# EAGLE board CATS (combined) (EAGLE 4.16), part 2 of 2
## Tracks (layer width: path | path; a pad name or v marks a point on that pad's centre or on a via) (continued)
N$10  (via drill 0.51) (continued)
  Bottom 0.18: TP4.T@3 42,34.5
  Bottom 0.36: 42,34.5 v42,77
  Bottom 2: TP4.T@1 TP4.T@2 TP4.T@3 TP4.T@4
N$11
  Top 0.18: R10.1 35.05,91.05 35,91 R7.2 33.05,91.05 33,91.1 | 33,91.1 C3.2 | 33,91.1 29.4,91.1 26.7,93.8 26.7,94 26.5,94.2 25.5,94.2 25.4,94.3 25.4,94.27 IC3.6
N$12
  Top 0.18: IC3.2 33,93 C3.1 34,92.95 | R7.1 35,92.9 34.95,92.95 34,92.95 | 34,92.95 R6.2
N$13
  Top 0.18: C7.2 39.05,92.95 39,93 R11.2 37.05,92.95 37,93 | IC5.3 44.73,100.27 44,101 38,101 37,100 37,93 | R10.2 37,93
N$14  (via drill 0.51)
  Top 0.18: 6,81 R14.1 3.05,81.05 3,81 | v3,77 3,81 | 3,81 Q1.3
  Bottom 0.18: 3.2,34.5 3.1,34.6 TP3.T@4 3,34.5
  Bottom 0.36: 3,34.5 v3,77
  Bottom 2: TP3.T@1 TP3.T@2 TP3.T@3 3.2,34.5
N$15
  Top 0.18: Q1.1 3.95,85 4,85 4.05,85.05 R12.1
N$16
  Top 0.18: 61.7,101.05 61.05,101.05 D2.C | 61.7,101.05 R26.2 64.95,101.05 65,101 C13.2 66.95,101.05 67,101 R23.2 | 61.7,101.05 61.7,101 61.73,100.97 IC9.3
N$17  (via drill 0.51)
  Top 0.18: v48,77 48,81 | 48,81 Q2.3 | R15.1 47.95,81.05 48,81
  Bottom 0.18: TP5.T@4 48,34.5
  Bottom 0.36: 48,34.5 v48,77
  Bottom 2: TP5.T@1 TP5.T@2 TP5.T@3 TP5.T@4
N$18
  Top 0.18: R17.1 49,87 48.95,86.95 Q2.1
N$19
  Top 0.18: R27.1 67.05,96.95 67,96.9 | IC9.2 63,97.3 63.4,96.9 67,96.9 | 67,96.9 C14.1
N$20
  Top 0.18: C14.2 67,95 66.9,95.1 62.2,95.1 61.73,94.63 IC9.6 61.73,91.73 61,91 61,87 | R30.2 61,87 | 61,87 65.25,87 68,84.25 R31.1 68,80.75
N$21  (via drill 0.51)
  Top 0.18: v68,77 R31.2
  Bottom 0.18: TP7.T@2 71.9,19.6 71.8,19.5 | TP7.T@4 68,34.5
  Bottom 0.36: 68,34.5 v68,77
  Bottom 2: TP7.T@1 71.8,19.5 | TP7.T@2 TP7.T@3 TP7.T@4
N$22
  Bottom 0.18: D14.K 93.05,102.7 93,102.75 D13.A 90.3,102.7 90,103 R21.1
N$23  (via drill 0.51)
  Top 0.18: IC6.1 92.06,86 92,86 v92,77
  Bottom 0.36: R22.SENSE2 88.3,53.3 92,57 v92,77
N$24
  Top 0.36: R22.SENSE1 86.54,78.5 86.5,78.5 87.61,79.61 IC6.8
N$25
  Top 0.18: IC6.2 90.16,86.54 89.6,87.1 87.8,87.1 87.7,87.17 IC6.6
N$26
  Top 4: TP6.T@1 TP6.T@4 80.2,34.5 | TP6.T@2 TP6.T@3 80.2,34.5 | 80.2,34.5 80.19,34.5
  Top 7.6: 80.19,34.5 R22.CURRENT2
  Bottom 4: TP6.T@1 TP6.T@4 | TP6.T@3 TP6.T@2
  Bottom 7.6: R22.CURRENT2 80.19,34.5
N$27
  Top 0.18: IC7.3 82.63,88.27 83,87.9 R20.2 84.95,87.95 85,87.9 R19.1 87.45,87.95 IC6.5
N$28
  Top 0.18: R27.2 69,92.5 73.23,88.27 IC7.6 74.4,88.27 74.3,88.2 76.4,88.2 76.55,88.05 | IC7.2 77.6,87 76.55,88.05 | R36.2 96.45,95.05 97.5,94 97.5,90 97,89.5 82.5,89.5 81.5,90.5 77.5,90.5 76.5,89.5 76.5,88 76.55,88 76.55,88.05
N$29
  Top 0.18: 101,97.3 IC10.2 | 101,97.3 101.4,96.9 104.9,96.9 105,97 C18.1 | R36.1 100.65,96.95 101,97.3
N$30
  Top 0.18: C18.2 105,95 104.9,95.1 100,95.1 99.73,94.83 IC10.6 99.73,87 | 99.73,87 99.73,86.98 97,84.25 R34.1 | 99.73,87 R35.2
N$31  (via drill 0.51)
  Top 0.18: v97,77 R34.2
  Bottom 0.18: TP9.T@3 97,34.5
  Bottom 0.36: 97,34.5 v97,77
  Bottom 2: TP9.T@1 TP9.T@2 TP9.T@3 TP9.T@4
N$32
  Top 0.18: R28.1 90.05,91.05 90,91 R25.2 88.05,91.05 88,91.1 | 88,91.1 C12.2 | 88,91.1 84.4,91.1 81.7,93.8 81.7,94 81.5,94.2 80.5,94.2 80.4,94.3 80.4,94.27 IC8.6
N$33
  Top 0.18: IC8.2 88,93 C12.1 89,92.95 | R25.1 90,92.9 89.95,92.95 89,92.95 | 89,92.95 R24.2
N$34
  Top 0.18: 89,96.9 R24.1 89,103.05 81.95,103.05 J2.CONDUCTOR 77.95,102.95 R23.1
  Bottom 0.18: R21.2 89.95,104.95 88,103 82,103 J2.CONDUCTOR
N$35
  Top 0.18: C16.2 94.05,92.95 94,93 R29.2 92.05,92.95 92,93 | IC10.3 99.73,100.27 99,101 93,101 92,100 92,93 | R28.2 92,93
N$36  (via drill 0.51)
  Top 0.18: 61,81 R32.1 58.05,81.05 58,81 | v58,77 58,81 | 58,81 Q3.3
  Bottom 0.18: 58.2,34.5 58.1,34.6 TP8.T@4 58,34.5
  Bottom 0.36: 58,34.5 v58,77
  Bottom 2: TP8.T@1 TP8.T@2 TP8.T@3 58.2,34.5
N$37
  Top 0.18: Q3.1 58.95,85 59,85 59.05,85.05 R30.1
N$38  (via drill 0.51)
  Top 0.18: v103,77 103,81 | 103,81 Q4.3 | R33.1 102.95,81.05 103,81
  Bottom 0.18: TP10.T@4 103,34.5
  Bottom 0.36: 103,34.5 v103,77
  Bottom 2: TP10.T@1 TP10.T@2 TP10.T@3 TP10.T@4
N$39
  Top 0.18: R35.1 104,87 103.95,86.95 Q4.1
N$40
  Top 0.18: 116.7,101.05 116.05,101.05 D5.C | 116.7,101.05 R41.2 119.95,101.05 120,101 C27.2 121.95,101.05 122,101 R40.2 | 116.7,101.05 116.7,101 116.73,100.97 IC13.3
N$41
  Top 0.18: R42.1 122.05,96.95 122,96.9 | IC13.2 118,97.3 118.4,96.9 122,96.9 | 122,96.9 C28.1
N$42
  Top 0.18: C28.2 122,95 121.9,95.1 117.2,95.1 116.73,94.63 IC13.6 116.73,91.73 116,91 116,87 | R55.2 116,87 | 116,87 120.25,87 123,84.25 R43.1 123,80.75
N$43  (via drill 0.51)
  Top 0.18: v123,77 R43.2
  Bottom 0.18: TP12.T@2 126.9,19.6 126.8,19.5 | TP12.T@4 123,34.5
  Bottom 0.36: 123,34.5 v123,77
  Bottom 2: TP12.T@1 126.8,19.5 | TP12.T@2 TP12.T@3 TP12.T@4
N$44
  Bottom 0.18: D16.K 148.05,102.7 148,102.75 D15.A 145.3,102.7 145,103 R53.1
N$45  (via drill 0.51)
  Top 0.18: IC14.1 147.06,86 147,86 v147,77
  Bottom 0.36: R45.SENSE2 143.3,53.3 147,57 v147,77
N$46
  Top 0.36: R45.SENSE1 141.54,78.5 141.5,78.5 142.61,79.61 IC14.8
N$47
  Top 0.18: IC14.2 145.16,86.54 144.6,87.1 142.8,87.1 142.7,87.17 IC14.6
N$48
  Top 4: TP13.T@1 TP13.T@4 135.2,34.5 | TP13.T@2 TP13.T@3 135.2,34.5 | 135.2,34.5 135.19,34.5
  Top 7.6: 135.19,34.5 R45.CURRENT2
  Bottom 4: TP13.T@1 TP13.T@4 | TP13.T@3 TP13.T@2
  Bottom 7.6: R45.CURRENT2 135.19,34.5
N$49
  Top 0.18: IC15.3 137.63,88.27 138,87.9 R44.2 139.95,87.95 140,87.9 R46.1 142.45,87.95 IC14.5
N$50
  Top 0.18: R42.2 124,92.5 128.23,88.27 IC15.6 129.4,88.27 129.3,88.2 131.4,88.2 131.55,88.05 | IC15.2 132.6,87 131.55,88.05 | R50.2 151.45,95.05 152.5,94 152.5,90 152,89.5 137.5,89.5 136.5,90.5 132.5,90.5 131.5,89.5 131.5,88 131.55,88 131.55,88.05
N$51
  Top 0.18: 156,97.3 IC16.2 | 156,97.3 156.4,96.9 159.9,96.9 160,97 C31.1 | R50.1 155.65,96.95 156,97.3
N$52
  Top 0.18: C31.2 160,95 159.9,95.1 155,95.1 154.73,94.83 IC16.6 154.73,87 | 154.73,87 154.73,86.98 152,84.25 R47.1 | 154.73,87 R57.2
N$53  (via drill 0.51)
  Top 0.18: v152,77 R47.2
  Bottom 0.18: TP14.T@3 152,34.5
  Bottom 0.36: 152,34.5 v152,77
  Bottom 2: TP14.T@1 TP14.T@2 TP14.T@3 TP14.T@4
N$54
  Top 0.18: R51.1 145.05,91.05 145,91 R48.2 143.05,91.05 143,91.1 | 143,91.1 C33.2 | 143,91.1 139.4,91.1 136.7,93.8 136.7,94 136.5,94.2 135.5,94.2 135.4,94.3 135.4,94.27 IC17.6
N$55
  Top 0.18: IC17.2 143,93 C33.1 144,92.95 | R48.1 145,92.9 144.95,92.95 144,92.95 | 144,92.95 R49.2
N$56
  Top 0.18: 144,96.9 R49.1 144,103.05 136.95,103.05 J3.CONDUCTOR 132.95,102.95 R40.1
  Bottom 0.18: R53.2 144.95,104.95 143,103 137,103 J3.CONDUCTOR
N$57
  Top 0.18: C34.2 149.05,92.95 149,93 R52.2 147.05,92.95 147,93 | IC16.3 154.73,100.27 154,101 148,101 147,100 147,93 | R51.2 147,93
N$58  (via drill 0.51)
  Top 0.18: 116,81 R54.1 113.05,81.05 113,81 | v113,77 113,81 | 113,81 Q5.3
  Bottom 0.18: 113.2,34.5 113.1,34.6 TP15.T@4 113,34.5
  Bottom 0.36: 113,34.5 v113,77
  Bottom 2: TP15.T@1 TP15.T@2 TP15.T@3 113.2,34.5
N$59
  Top 0.18: Q5.1 113.95,85 114,85 114.05,85.05 R55.1
N$60  (via drill 0.51)
  Top 0.18: v158,77 158,81 | 158,81 Q6.3 | R56.1 157.95,81.05 158,81
  Bottom 0.18: TP16.T@4 158,34.5
  Bottom 0.36: 158,34.5 v158,77
  Bottom 2: TP16.T@1 TP16.T@2 TP16.T@3 TP16.T@4
N$61
  Top 0.18: R57.1 159,87 158.95,86.95 Q6.1
N$62
  Top 0.18: 171.7,101.05 171.05,101.05 D6.C | 171.7,101.05 R59.2 174.95,101.05 175,101 C36.2 176.95,101.05 177,101 R58.2 | 171.7,101.05 171.7,101 171.73,100.97 IC18.3
N$63
  Top 0.18: R60.1 177.05,96.95 177,96.9 | IC18.2 173,97.3 173.4,96.9 177,96.9 | 177,96.9 C37.1
N$64
  Top 0.18: C37.2 177,95 176.9,95.1 172.2,95.1 171.73,94.63 IC18.6 171.73,91.73 171,91 171,87 | R73.2 171,87 | 171,87 175.25,87 178,84.25 R61.1 178,80.75
N$65  (via drill 0.51)
  Top 0.18: v178,77 R61.2
  Bottom 0.18: TP17.T@2 181.9,19.6 181.8,19.5 | 178,34.5 TP17.T@4
  Bottom 0.36: v178,77 178,34.5
  Bottom 2: 181.8,19.5 TP17.T@1 | TP17.T@2 TP17.T@3 TP17.T@4
N$66
  Bottom 0.18: D18.K 203.05,102.7 203,102.75 D17.A 200.3,102.7 200,103 R71.1
N$67  (via drill 0.51)
  Top 0.18: IC19.1 202.06,86 202,86 v202,77
  Bottom 0.36: R63.SENSE2 198.3,53.3 202,57 v202,77
N$68
  Top 0.36: R63.SENSE1 196.54,78.5 196.5,78.5 197.61,79.61 IC19.8
N$69
  Top 0.18: IC19.2 200.16,86.54 199.6,87.1 197.8,87.1 197.7,87.17 IC19.6
N$70
  Top 4: TP18.T@1 TP18.T@4 190.2,34.5 | TP18.T@2 TP18.T@3 190.2,34.5 | 190.2,34.5 190.19,34.5
  Top 7.6: 190.19,34.5 R63.CURRENT2
  Bottom 4: TP18.T@1 TP18.T@4 | TP18.T@3 TP18.T@2
  Bottom 7.6: R63.CURRENT2 190.19,34.5
N$71
  Top 0.18: IC20.3 192.63,88.27 193,87.9 R62.2 194.95,87.95 195,87.9 R64.1 197.45,87.95 IC19.5
N$72
  Top 0.18: R60.2 179,92.5 183.23,88.27 IC20.6 184.4,88.27 184.3,88.2 186.4,88.2 186.55,88.05 | IC20.2 187.6,87 186.55,88.05 | R68.2 206.45,95.05 207.5,94 207.5,90 207,89.5 192.5,89.5 191.5,90.5 187.5,90.5 186.5,89.5 186.5,88 186.55,88 186.55,88.05
N$73
  Top 0.18: 211,97.3 IC21.2 | 211,97.3 211.4,96.9 214.9,96.9 215,97 C40.1 | R68.1 210.65,96.95 211,97.3
N$74
  Top 0.18: C40.2 215,95 214.9,95.1 210,95.1 209.73,94.83 IC21.6 209.73,87 | 209.73,87 209.73,86.98 207,84.25 R65.1 | 209.73,87 R75.2
N$75  (via drill 0.51)
  Top 0.18: v207,77 R65.2
  Bottom 0.18: 207,34.5 TP19.T@3
  Bottom 0.36: v207,77 207,34.5
  Bottom 2: TP19.T@1 TP19.T@2 TP19.T@3 TP19.T@4
N$76
  Top 0.18: R69.1 200.05,91.05 200,91 R66.2 198.05,91.05 198,91.1 | 198,91.1 C42.2 | 198,91.1 194.4,91.1 191.7,93.8 191.7,94 191.5,94.2 190.5,94.2 190.4,94.3 190.4,94.27 IC22.6
N$77
  Top 0.18: IC22.2 198,93 C42.1 199,92.95 | R66.1 200,92.9 199.95,92.95 199,92.95 | 199,92.95 R67.2
N$78
  Top 0.18: 199,96.9 R67.1 199,103.05 191.95,103.05 J4.CONDUCTOR 187.95,102.95 R58.1
  Bottom 0.18: R71.2 199.7,104.95 197.75,103 191.75,103 190,104.75 J4.CONDUCTOR
N$79
  Top 0.18: C43.2 204.05,92.95 204,93 R70.2 202.05,92.95 202,93 | IC21.3 209.73,100.27 209,101 203,101 202,100 202,93 | R69.2 202,93
N$80  (via drill 0.51)
  Top 0.18: 171,81 R72.1 168.05,81.05 168,81 | v168,77 168,81 | 168,81 Q7.3
  Bottom 0.18: 168.2,34.5 168.1,34.6 TP20.T@4 168,34.5
  Bottom 0.36: 168,34.5 v168,77
  Bottom 2: TP20.T@1 TP20.T@2 TP20.T@3 168.2,34.5
N$81
  Top 0.18: Q7.1 168.95,85 169,85 169.05,85.05 R73.1
N$82  (via drill 0.51)
  Top 0.18: 213,81 v213,77 | 213,81 Q8.3 | R74.1 212.95,81.05 213,81
  Bottom 0.18: 213,34.5 TP21.T@4
  Bottom 0.36: v213,77 213,34.5
  Bottom 2: TP21.T@1 TP21.T@2 TP21.T@3 TP21.T@4
N$83
  Top 0.18: R75.1 214,87 213.95,86.95 Q8.1
N$84
  Top 0.18: 226.7,101.05 226.05,101.05 D7.C | 226.7,101.05 R77.2 229.95,101.05 230,101 C45.2 232.05,101.05 232.25,101.25 R76.2 | 226.7,101.05 226.7,101 226.73,100.97 IC23.3
N$85
  Top 0.18: R78.1 232.05,96.95 232,96.9 | IC23.2 228,97.3 228.4,96.9 232,96.9 | 232,96.9 C46.1
N$86
  Top 0.18: C46.2 232,95 231.9,95.1 227.2,95.1 226.73,94.63 IC23.6 226.73,91.73 226,91 226,87 | R91.2 226,87 | 226,87 230.25,87 233,84.25 R79.1 233,80.75
N$87  (via drill 0.51)
  Top 0.18: v233,77 R79.2
  Bottom 0.18: TP22.T@2 236.9,19.6 236.8,19.5 | TP22.T@4 233,34.5
  Bottom 0.36: 233,34.5 v233,77
  Bottom 2: 236.8,19.5 TP22.T@1 | TP22.T@2 TP22.T@3 TP22.T@4
N$88
  Bottom 0.18: D19.A 257.75,102.7 257.75,102.75 257.8,102.7 D19.A | D19.A D20.K | R89.1 255,103 255.3,102.7 D19.A
N$89  (via drill 0.51)
  Top 0.18: IC24.1 257.06,86 257,86 v257,77
  Bottom 0.36: R81.SENSE2 253.3,53.3 257,57 v257,77
N$90
  Top 0.36: R81.SENSE1 251.54,78.5 251.5,78.5 252.61,79.61 IC24.8
N$91
  Top 0.18: IC24.2 255.16,86.54 254.6,87.1 252.8,87.1 252.7,87.17 IC24.6
N$92
  Top 4: TP23.T@1 TP23.T@4 245.2,34.5 | TP23.T@2 TP23.T@3 245.2,34.5 | 245.2,34.5 245.19,34.5
  Top 7.6: 245.19,34.5 R81.CURRENT2
  Bottom 4: TP23.T@1 TP23.T@4 | TP23.T@3 TP23.T@2
  Bottom 7.6: R81.CURRENT2 245.19,34.5
N$93
  Top 0.18: IC25.3 247.63,88.27 248,87.9 R80.2 249.95,87.95 250,87.9 R82.1 252.45,87.95 IC24.5
N$94
  Top 0.18: R78.2 234,92.5 238.23,88.27 IC25.6 239.4,88.27 239.3,88.2 241.4,88.2 241.55,88.05 | IC25.2 242.6,87 241.55,88.05 | 241.55,88.05 241.55,88 241.5,88 241.5,89.5 242.5,90.5 246.5,90.5 247.5,89.5 262,89.5 262.5,90 262.5,94.25 261.75,95 R86.2
N$95
  Top 0.18: 266,97.3 IC26.2 | 266,97.3 266.4,96.9 269.9,96.9 270,97 C49.1 | R86.1 259.05,95.55 259.75,96.25 265,96.25 266,97.25 266,97.3
N$96
  Top 0.18: C49.2 270,95 269.9,95.1 265,95.1 264.73,94.83 IC26.6 264.73,87 | 264.73,87 264.73,86.98 262,84.25 R83.1 | 264.73,87 R93.2
N$97  (via drill 0.51)
  Top 0.18: v262,77 R83.2
  Bottom 0.18: TP24.T@3 262,34.5
  Bottom 0.36: 262,34.5 v262,77
  Bottom 2: TP24.T@1 TP24.T@2 TP24.T@3 TP24.T@4
N$98
  Top 0.18: R87.1 255.05,91.05 255,91 R84.2 253.05,91.05 253,91.1 | 253,91.1 C51.2 | 253,91.1 249.4,91.1 246.7,93.8 246.7,94 246.5,94.2 245.5,94.2 245.4,94.3 245.4,94.27 IC27.6
N$99
  Top 0.18: IC27.2 253,93 C51.1 254,92.95 | R84.1 255,92.9 254.95,92.95 254,92.95 | 254,92.95 R85.2
N$100
  Top 0.18: 254,96.9 R85.1 254,103.05 246.95,103.05 J5.CONDUCTOR 242.95,102.95 R76.1
  Bottom 0.18: R89.2 254.95,104.95 253,103 247,103 J5.CONDUCTOR
N$101
  Top 0.18: C52.2 259.05,92.95 259,93 R88.2 257.75,92.95 | 257.75,92.95 257.05,92.95 257,93 R87.2 | IC26.3 264.73,97.48 264,96.75 258.5,96.75 257.75,96 257.75,92.95
N$102  (via drill 0.51)
  Top 0.18: 226,81 R90.1 223.05,81.05 223,81 | v223,77 223,81 | 223,81 Q9.3
  Bottom 0.18: 223.2,34.5 223.1,34.6 TP25.T@4 223,34.5
  Bottom 0.36: 223,34.5 v223,77
  Bottom 2: TP25.T@1 TP25.T@2 TP25.T@3 223.2,34.5
N$103
  Top 0.18: Q9.1 223.95,85 224,85 224.05,85.05 R91.1
N$104  (via drill 0.51)
  Top 0.18: v268,77 268,81 | 268,81 Q10.3 | R92.1 267.95,81.05 268,81
  Bottom 0.18: TP26.T@4 268,34.5
  Bottom 0.36: 268,34.5 v268,77
  Bottom 2: TP26.T@1 TP26.T@2 TP26.T@3 TP26.T@4
N$105
  Top 0.18: R93.1 269,87 268.95,86.95 Q10.1
N$106
  Top 0.4: 55,0 55,12
N$107
  Top 0.4: 110,0 110,12
N$108
  Top 0.4: 165,0 165,12
N$109
  Top 0.4: 220,0 220,12
N$110
  Top 0.18: 6.7,101.05 6.05,101.05 D1.C | 6.7,101.05 R8.2 9.95,101.05 10,101 C4.2 R5.2 12,101 | 6.7,101.05 6.7,101 6.73,100.97 IC4.3
N$111
  Top 0.4: 275,0 275,12
N$112
  Bottom 0.5: P1.9 310.16,91.66 308,89.5 305.5,89.5 305,89 305,58 298,51 | 293,51 298,51 | 298,51 F1.1A
N$113
  Top 0.18: D8.A 303.77,94.77 304,95 R94.2 307,95 307.25,94.75 307.32,94.75 P1.4
N$114
  Top 0.18: R9.1 12.05,96.95 12,96.9 | IC4.2 8,97.3 8.4,96.9 12,96.9 | 12,96.9 C5.1
N$115
  Top 0.18: C5.2 12,95 11.9,95.1 7.2,95.1 6.73,94.63 IC4.6 6.73,91.73 6,91 6,87 | R12.2 6,87 | 6,87 10.25,87 13,84.25 R13.1
N$116
  Bottom 0.36: 296,100.5 300.5,100.5 303,103 307.5,103 307.5,103.06 P1.1
  Bottom 0.5: 291,100.28 291,100.5 291.08,100.42 Q11.2 | 296,100.5 295.97,100.5 HS1.2
  Bottom 1: HS1.2 295.97,100 296,100 295.72,100.28 291,100.28 HS1.1
N$117  (via drill 0.51)
  Top 0.18: v13,77 R13.2
  Bottom 0.18: TP2.T@2 16.9,19.6 16.8,19.5 | TP2.T@4 13,34.5
  Bottom 0.36: 13,34.5 v13,77
  Bottom 2: TP2.T@1 16.8,19.5 | TP2.T@2 TP2.T@3 TP2.T@4
N$118
  Top 0.18: R96.CW 302.77,92.23 302.5,92.5 D8.C 300.75,93 | Q11.1 288.54,93.71 289.25,93 300.75,93 | D9.C 301.5,97 300.75,96.25 300.75,93
  Bottom 0.18: R96.W 300.2,86.9 302.74,89.44 R96.CW
N$119
  Top 0.18: D9.A 303.75,97 303.95,97.2 303.95,97.5 | R95.2 303.95,97.5 | 303.95,97.5 304,97.5 304.07,97.57 P1.3
N$120  (via drill 0.51)
  Top 0.18: P1.2 307.25,100.31 307.25,100.25 306.47,101.03 D10.3 | R97.1 293.55,86.95 v293.5,87
  Bottom 0.18: P1.2 307.25,100.31 307.25,100.25 294,87 v293.5,87
N$121
  Bottom 0.18: D11.A D12.K | D11.A 38,102.75 | R3.1 35,103 35.3,102.7 D11.A
N$122
  Top 0.18: J13.CONDUCTOR 11.49,218.5 11.5,218.5 9.99,216.99 R98.1
  Bottom 0.18: R174.2 21.55,211.05 20.5,210 15,210 11.5,213.5 11.5,218.5 11.49,218.5 J13.CONDUCTOR
N$123
  Top 0.178: 7.45,204.95 C54.2 R99.2 7.95,207.49 8.97,206.47 9.86,206.47 9.99,206.35 R98.2 11.7,206.41 12.02,206.09 | 12.02,206.09 D21.C | 12.02,206.09 12.02,205.2 12.91,204.31 14.3,204.31 14.43,204.19 IC28.3
N$124  (via drill 0.51)
  Top 0.178: v11.51,199.62 IC29.1
  Bottom 0.381: R102.SENSE2 11.51,189.71 14.3,192.5 14.3,194.66 11.51,197.46 v11.51,199.62
N$125  (via drill 0.51)
  Top 0.178: v10.11,199.62 9.22,200.5 7.32,200.5 7.19,200.63 IC29.8
  Bottom 0.381: R102.SENSE1 11.51,196.44 10.11,197.84 v10.11,199.62
N$126
  Top 0.178: IC29.6 9.35,201.9 9.99,201.27 IC29.2
N$127
  Top 0.178: R100.2 16.32,201 16.34,201.01 | 14.43,205.33 14.3,205.46 IC28.2 14.43,205.46 14.3,205.33 15.7,205.33 16.34,204.7 16.34,201.01 | 16.34,201.01 C55.1 14.05,201.01 12.78,202.16 12.4,202.54 12.4,203.17 12.14,203.43 9.86,203.43 8.97,202.54 IC29.5 7.07,202.69 5.07,202.69 R190.1
N$128
  Top 0.178: 19.51,204.19 IC28.6 18.11,204.19 17.73,203.81 17.73,202.28 18.22,201.79 C55.2 18.11,201.01 18.18,200.95 R101.1
N$129
  Top 3.81: 6.81,149.2 TP27.T@3 | TP27.T@2 6.9,149.11 6.81,149.2 | TP27.T@4 3.1,149.32 3.13,149.32 3.1,149.3 TP27.T@4 | TP27.T@1 TP27.T@4 | TP27.T@4 3.1,149.07 3.13,149.07 3.25,149.2 6.81,149.2
  Top 7.62: R102.CURRENT2 5.16,149.32
  Bottom 2.54: 5.29,149.45 5.16,149.45 | 4.87,149.24 5.07,149.24 5.29,149.45 | 5.29,149.45 5.03,149.2 6.81,149.2 TP27.T@3
  Bottom 7.62: R102.CURRENT2 5.16,149.45 5.16,149.32 | 4.87,149.24 4.87,134.71
N$130  (via drill 0.51)
  Top 0.254: R101.2 20.57,198.3 v21.54,197.33
  Bottom 0.254: TP28.T@2 21.8,134.2 21.8,134.21 21.79,134.2 | TP28.T@3 21.8,149.2 21.9,149.09 | TP28.T@3 21.54,149.2 21.42,149.07 21.29,149.2 | 21.92,149.07 21.9,149.07 TP28.T@3
  Bottom 0.381: v21.54,197.33 21.92,196.95 21.92,149.07
  Bottom 2.54: TP28.T@1 21.79,134.2 | TP28.T@2 21.9,149.09 | 21.29,149.2 TP28.T@4
N$131
  Top 0.18: J11.CONDUCTOR 36.49,218.25 36.5,218.25 34.99,216.74 R103.1
  Bottom 0.18: R173.2 46.55,211.05 45.5,210 40,210 36.5,213.5 36.5,218 36.49,218 J11.CONDUCTOR
N$132
  Top 0.178: 32.45,204.95 C57.2 R104.2 32.95,207.49 33.97,206.47 34.86,206.47 34.99,206.35 R103.2 36.7,206.41 37.02,206.09 | 37.02,206.09 D22.C | 37.02,206.09 37.02,205.2 37.91,204.31 39.3,204.31 39.43,204.19 IC30.3
N$133  (via drill 0.51)
  Top 0.178: v36.51,199.62 IC31.1
  Bottom 0.381: R107.SENSE2 36.51,189.71 39.3,192.5 39.3,194.66 36.51,197.46 v36.51,199.62
N$134  (via drill 0.51)
  Top 0.178: v35.11,199.62 34.22,200.5 32.32,200.5 32.19,200.63 IC31.8
  Bottom 0.381: R107.SENSE1 36.51,196.44 35.11,197.84 v35.11,199.62
N$135
  Top 0.178: IC31.6 34.35,201.9 34.99,201.27 IC31.2
N$136
  Top 0.178: R105.2 41.32,201 41.34,201.01 | 39.43,205.33 39.3,205.46 IC30.2 39.43,205.46 39.3,205.33 40.7,205.33 41.34,204.7 41.34,201.01 | 41.34,201.01 C58.1 39.05,201.01 37.78,202.16 37.4,202.54 37.4,203.17 37.15,203.43 34.86,203.43 33.97,202.54 IC31.5 32.06,202.82 30.07,202.82 R189.1
N$137
  Top 0.178: 44.51,204.19 IC30.6 43.11,204.19 42.73,203.81 42.73,202.28 43.22,201.79 C58.2 43.11,201.01 43.18,200.95 R106.1
N$138
  Top 3.81: 31.81,149.2 TP29.T@3 | TP29.T@2 31.9,149.11 31.81,149.2 | TP29.T@4 28.1,149.32 28.13,149.32 28.1,149.3 TP29.T@4 | TP29.T@1 TP29.T@4 | TP29.T@4 28.1,149.07 28.13,149.07 28.25,149.2 31.81,149.2
  Top 7.62: R107.CURRENT2 30.16,149.32
  Bottom 2.54: 30.29,149.45 30.16,149.45 | 29.87,149.24 30.07,149.24 30.29,149.45 | 30.29,149.45 30.03,149.2 31.81,149.2 TP29.T@3
  Bottom 7.62: R107.CURRENT2 30.16,149.45 30.16,149.32 | 29.87,149.24 29.87,134.71
N$139  (via drill 0.51)
  Top 0.254: R106.2 45.57,198.3 v46.54,197.33
  Bottom 0.254: TP30.T@2 46.8,134.2 46.8,134.21 46.79,134.2 | TP30.T@3 46.8,149.2 46.9,149.09 | TP30.T@3 46.54,149.2 46.42,149.07 46.29,149.2 | 46.92,149.07 46.9,149.07 TP30.T@3
  Bottom 0.381: v46.54,197.33 46.92,196.95 46.92,149.07
  Bottom 2.54: TP30.T@1 46.79,134.2 | TP30.T@2 46.9,149.09 | 46.29,149.2 TP30.T@4
N$140
  Top 0.18: J9.CONDUCTOR 61.49,218.25 61.5,218.25 59.99,216.74 R108.1
  Bottom 0.18: R171.2 71.55,211.05 70.5,210 65,210 61.5,213.5 61.5,218 61.49,218 J9.CONDUCTOR
N$141
  Top 0.178: 57.45,204.95 C60.2 R109.2 57.95,207.49 58.97,206.47 59.86,206.47 59.99,206.35 R108.2 61.7,206.41 62.02,206.09 | 62.02,206.09 D23.C | 62.02,206.09 62.02,205.2 62.91,204.31 64.3,204.31 64.43,204.19 IC32.3
N$142  (via drill 0.51)
  Top 0.178: v61.51,199.62 IC33.1
  Bottom 0.381: R112.SENSE2 61.51,189.71 64.3,192.5 64.3,194.66 61.51,197.46 v61.51,199.62
N$143  (via drill 0.51)
  Top 0.178: v60.11,199.62 59.22,200.5 57.32,200.5 57.19,200.63 IC33.8
  Bottom 0.381: R112.SENSE1 61.51,196.44 60.11,197.84 v60.11,199.62
N$144
  Top 0.178: IC33.6 59.35,201.9 59.99,201.27 IC33.2
N$145  (via drill 0.51)
  Top 0.18: 277.6,109.5 277.5,109.5 277.46,109.54 IC11.3 | 277.6,109.5 C19.2 | 277.6,109.5 277.6,109.16 v279.25,107.5
  Bottom 0.18: F1.2A 277.84,50.9 277.8,50.9 277.9,50.8 | v279.25,107.5 279.25,98.75 287,91 287,77 289.8,74.2 289.8,65.9 291,64.7 292,64.7
  Bottom 0.5: D3.2 292,64.7 292,59.6 283.2,50.8 277.9,50.8
N$146
  Top 0.18: C20.2 277,102.5 | C20.2 R38.1 | C20.2 275.05,102.7 275,102.75 R37.2 275,103.5 274,104.5 IC11.1
N$147
  Top 0.178: R110.2 66.32,201 66.34,201.01 | 64.43,205.33 64.3,205.46 IC32.2 64.43,205.46 64.3,205.33 65.7,205.33 66.34,204.7 66.34,201.01 | 66.34,201.01 C61.1 64.05,201.01 62.78,202.16 62.4,202.54 62.4,203.17 62.15,203.43 59.86,203.43 58.97,202.54 IC33.5 57.06,202.82 55.07,202.82 R188.1
N$148
  Top 0.178: 69.51,204.19 IC32.6 68.11,204.19 67.73,203.81 67.73,202.28 68.22,201.79 C61.2 68.11,201.01 68.18,200.95 R111.1
N$149
  Top 3.81: 56.81,149.2 TP31.T@3 | TP31.T@2 56.9,149.11 56.81,149.2 | TP31.T@4 53.1,149.32 53.13,149.32 53.1,149.3 TP31.T@4 | TP31.T@1 TP31.T@4 | TP31.T@4 53.1,149.07 53.13,149.07 53.26,149.2 56.81,149.2
  Top 7.62: R112.CURRENT2 55.16,149.32
  Bottom 2.54: 55.29,149.45 55.16,149.45 | 54.87,149.24 55.07,149.24 55.29,149.45 | 55.29,149.45 55.03,149.2 56.81,149.2 TP31.T@3
  Bottom 7.62: R112.CURRENT2 55.16,149.45 55.16,149.32 | 54.87,149.24 54.87,134.71
N$150  (via drill 0.51)
  Top 0.254: R111.2 70.57,198.3 v71.54,197.33
  Bottom 0.254: TP32.T@2 71.8,134.2 71.8,134.21 71.79,134.2 | TP32.T@3 71.8,149.2 71.9,149.09 | TP32.T@3 71.54,149.2 71.42,149.07 71.29,149.2 | 71.92,149.07 71.9,149.07 TP32.T@3
  Bottom 0.381: v71.54,197.33 71.92,196.95 71.92,149.07
  Bottom 2.54: 71.79,134.2 TP32.T@1 | 71.9,149.09 TP32.T@2 | 71.29,149.2 TP32.T@4
N$151
  Top 0.18: J12.CONDUCTOR 86.49,218.25 86.5,218.25 84.99,216.74 R113.1
  Bottom 0.18: R175.2 96.55,211.05 95.5,210 90,210 86.5,213.5 86.5,218.5 86.49,218.5 J12.CONDUCTOR
N$152
  Top 0.178: 82.45,204.95 C63.2 R114.2 82.95,207.49 83.97,206.47 84.86,206.47 84.99,206.35 R113.2 86.7,206.41 87.02,206.09 | 87.02,206.09 D24.C | 87.02,206.09 87.02,205.2 87.91,204.31 89.3,204.31 89.43,204.19 IC34.3
N$153  (via drill 0.51)
  Top 0.178: v86.51,199.62 IC35.1
  Bottom 0.381: R117.SENSE2 86.51,189.71 89.3,192.5 89.3,194.66 86.51,197.46 v86.51,199.62
N$154  (via drill 0.51)
  Top 0.178: v85.11,199.62 84.22,200.5 82.32,200.5 82.19,200.63 IC35.8
  Bottom 0.381: R117.SENSE1 86.51,196.44 85.11,197.84 v85.11,199.62
N$155
  Top 0.178: IC35.6 84.35,201.9 84.99,201.27 IC35.2
N$156
  Top 0.178: R115.2 91.32,201 91.34,201.01 | 89.43,205.33 89.3,205.46 IC34.2 89.43,205.46 89.3,205.33 90.7,205.33 91.34,204.7 91.34,201.01 | 91.34,201.01 C64.1 89.05,201.01 87.78,202.16 87.4,202.54 87.4,203.17 87.14,203.43 84.86,203.43 83.97,202.54 IC35.5 82.06,202.82 80.07,202.82 R187.1
N$157
  Top 0.178: 94.51,204.19 IC34.6 93.11,204.19 92.73,203.81 92.73,202.28 93.22,201.79 C64.2 93.11,201.01 93.18,200.95 R116.1
N$158
  Top 3.81: 81.81,149.2 TP33.T@3 | TP33.T@2 81.9,149.11 81.81,149.2 | TP33.T@4 78.1,149.32 78.13,149.32 78.1,149.3 TP33.T@4 | TP33.T@1 TP33.T@4 | TP33.T@4 78.1,149.07 78.13,149.07 78.25,149.2 81.81,149.2
  Top 7.62: R117.CURRENT2 80.16,149.32
  Bottom 2.54: 80.29,149.45 80.16,149.45 | 79.87,149.24 80.07,149.24 80.29,149.45 | 80.29,149.45 80.03,149.2 81.81,149.2 TP33.T@3
  Bottom 7.62: R117.CURRENT2 80.16,149.45 80.16,149.32 | 79.87,149.24 79.87,134.71
N$159  (via drill 0.51)
  Top 0.254: R116.2 95.57,198.3 v96.54,197.33
  Bottom 0.254: TP34.T@2 96.8,134.2 96.8,134.21 96.79,134.2 | TP34.T@3 96.8,149.2 96.9,149.09 | TP34.T@3 96.54,149.2 96.42,149.07 96.29,149.2 | 96.92,149.07 96.9,149.07 TP34.T@3
  Bottom 0.381: v96.54,197.33 96.92,196.95 96.92,149.07
  Bottom 2.54: 96.79,134.2 TP34.T@1 | 96.9,149.09 TP34.T@2 | 96.29,149.2 TP34.T@4
N$160
  Top 0.18: J10.CONDUCTOR 111.49,218.5 111.5,218.5 109.99,216.99 R118.1
  Bottom 0.18: R172.2 121.55,211.05 120.5,210 115,210 111.5,213.5 111.5,218.5 111.49,218.5 J10.CONDUCTOR
N$161
  Top 0.178: 107.45,204.95 C66.2 R119.2 107.95,207.49 108.97,206.47 109.86,206.47 109.99,206.35 R118.2 111.7,206.41 112.02,206.09 | 112.02,206.09 D25.C | 112.02,206.09 112.02,205.2 112.91,204.31 114.3,204.31 114.43,204.19 IC36.3
N$162  (via drill 0.51)
  Top 0.178: v111.51,199.62 IC37.1
  Bottom 0.381: R122.SENSE2 111.51,189.71 114.3,192.5 114.3,194.66 111.51,197.46 v111.51,199.62
N$163  (via drill 0.51)
  Top 0.178: v110.11,199.62 109.22,200.5 107.32,200.5 107.19,200.63 IC37.8
  Bottom 0.381: R122.SENSE1 111.51,196.44 110.11,197.84 v110.11,199.62
N$164
  Top 0.178: IC37.6 109.35,201.9 109.99,201.27 IC37.2
N$165
  Top 0.178: R120.2 116.32,201 116.34,201.01 | 114.43,205.33 114.3,205.46 IC36.2 114.43,205.46 114.3,205.33 115.7,205.33 116.34,204.7 116.34,201.01 | 116.34,201.01 C67.1 114.05,201.01 112.78,202.16 112.4,202.54 112.4,203.17 112.14,203.43 109.86,203.43 108.97,202.54 IC37.5 107.06,202.82 105.07,202.82 R186.1
N$166
  Top 0.178: 119.51,204.19 IC36.6 118.11,204.19 117.73,203.81 117.73,202.28 118.22,201.79 C67.2 118.11,201.01 118.18,200.95 R121.1
N$167
  Top 3.81: 106.81,149.2 TP35.T@3 | TP35.T@2 106.9,149.11 106.81,149.2 | TP35.T@4 103.1,149.32 103.13,149.32 103.1,149.3 TP35.T@4 | TP35.T@4 TP35.T@1 | TP35.T@4 103.1,149.07 103.13,149.07 103.25,149.2 106.81,149.2
  Top 7.62: R122.CURRENT2 105.16,149.32
  Bottom 2.54: 105.29,149.45 105.16,149.45 | 104.87,149.24 105.07,149.24 105.29,149.45 | 105.29,149.45 105.03,149.2 106.81,149.2 TP35.T@3
  Bottom 7.62: R122.CURRENT2 105.16,149.45 105.16,149.32 | 104.87,149.24 104.87,134.71
N$168  (via drill 0.51)
  Top 0.254: R121.2 120.57,198.3 v121.54,197.33
  Bottom 0.254: TP36.T@2 121.8,134.2 121.8,134.21 121.79,134.2 | TP36.T@3 121.8,149.2 121.9,149.09 | TP36.T@3 121.54,149.2 121.42,149.07 121.29,149.2 | 121.92,149.07 121.9,149.07 TP36.T@3 | 121.92,196.95 v121.54,197.33
  Bottom 0.381: 121.92,149.07 121.92,196.95
  Bottom 2.54: 121.79,134.2 TP36.T@1 | 121.9,149.09 TP36.T@2 | TP36.T@4 121.29,149.2
N$169
  Top 0.18: J8.CONDUCTOR 136.49,218.5 136.5,218.5 134.99,216.99 R123.1
  Bottom 0.18: R170.2 146.55,211.05 145.5,210 140,210 136.5,213.5 136.5,218.5 136.49,218.5 J8.CONDUCTOR
N$170
  Top 0.178: 132.45,204.95 C69.2 R124.2 132.95,207.49 133.97,206.47 134.86,206.47 134.99,206.35 R123.2 136.7,206.41 137.02,206.09 | 137.02,206.09 D26.C | 137.02,206.09 137.02,205.2 137.91,204.31 139.3,204.31 139.43,204.19 IC38.3
N$171  (via drill 0.51)
  Top 0.178: v136.51,199.62 IC39.1
  Bottom 0.381: R127.SENSE2 136.51,189.71 139.3,192.5 139.3,194.66 136.51,197.46 v136.51,199.62
N$172  (via drill 0.51)
  Top 0.178: v135.11,199.62 134.22,200.5 132.32,200.5 132.19,200.63 IC39.8
  Bottom 0.381: R127.SENSE1 136.51,196.44 135.11,197.84 v135.11,199.62
N$173
  Top 0.178: IC39.6 134.35,201.9 134.99,201.27 IC39.2
N$174
  Top 0.178: R125.2 141.32,201 141.34,201.01 | 139.43,205.33 139.3,205.46 IC38.2 139.43,205.46 139.3,205.33 140.7,205.33 141.34,204.7 141.34,201.01 | 141.34,201.01 C70.1 139.05,201.01 137.78,202.16 137.4,202.54 137.4,203.17 137.15,203.43 134.86,203.43 133.97,202.54 IC39.5 132.06,202.82 130.07,202.82 R185.1
N$175
  Top 0.178: 144.51,204.19 IC38.6 143.11,204.19 142.73,203.81 142.73,202.28 143.22,201.79 C70.2 143.11,201.01 143.18,200.95 R126.1
N$176
  Top 3.81: 131.81,149.2 TP37.T@3 | TP37.T@2 131.9,149.11 131.81,149.2 | TP37.T@4 128.1,149.32 128.13,149.32 128.1,149.3 TP37.T@4 | TP37.T@1 TP37.T@4 | TP37.T@4 128.1,149.07 128.13,149.07 128.25,149.2 131.81,149.2
  Top 7.62: R127.CURRENT2 130.16,149.32
  Bottom 2.54: 130.29,149.45 130.16,149.45 | 129.87,149.24 130.07,149.24 130.29,149.45 | 130.29,149.45 130.03,149.2 131.81,149.2 TP37.T@3
  Bottom 7.62: R127.CURRENT2 130.16,149.45 130.16,149.32 | 129.87,149.24 129.87,134.71
N$177  (via drill 0.51)
  Top 0.254: R126.2 145.57,198.3 v146.54,197.33
  Bottom 0.254: TP38.T@2 146.8,134.2 146.8,134.21 146.79,134.2 | TP38.T@3 146.8,149.2 146.9,149.09 | TP38.T@3 146.54,149.2 146.42,149.07 146.29,149.2 | 146.92,149.07 146.9,149.07 TP38.T@3 | 146.92,196.95 v146.54,197.33
  Bottom 0.381: 146.92,149.07 146.92,196.95
  Bottom 2.54: TP38.T@1 146.79,134.2 | TP38.T@2 146.9,149.09 | 146.29,149.2 TP38.T@4
N$178
  Top 0.18: J6.CONDUCTOR 161.49,218.25 161.5,218.25 159.99,216.74 R128.1
  Bottom 0.18: R165.2 171.55,211.05 170.5,210 165,210 161.5,213.5 161.5,218.5 161.49,218.5 J6.CONDUCTOR
N$179
  Top 0.178: 157.45,204.95 C72.2 R129.2 157.95,207.49 158.97,206.47 159.86,206.47 159.99,206.35 R128.2 161.7,206.41 162.02,206.09 | 162.02,206.09 D27.C | 162.02,206.09 162.02,205.2 162.91,204.31 164.3,204.31 164.43,204.19 IC40.3
N$180  (via drill 0.51)
  Top 0.178: v161.51,199.62 IC41.1
  Bottom 0.381: R132.SENSE2 161.51,189.71 164.3,192.5 164.3,194.66 161.51,197.46 v161.51,199.62
N$181  (via drill 0.51)
  Top 0.178: v160.11,199.62 159.22,200.5 157.32,200.5 157.19,200.63 IC41.8
  Bottom 0.381: R132.SENSE1 161.51,196.44 160.11,197.84 v160.11,199.62
N$182
  Top 0.178: IC41.6 159.35,201.9 159.99,201.27 IC41.2
N$183
  Top 0.178: R130.2 166.32,201 166.34,201.01 | 164.43,205.33 164.3,205.46 IC40.2 164.43,205.46 164.3,205.33 165.7,205.33 166.34,204.7 166.34,201.01 | 166.34,201.01 C73.1 164.05,201.01 162.78,202.16 162.4,202.54 162.4,203.17 162.15,203.43 159.86,203.43 158.97,202.54 IC41.5 157.06,202.82 155.07,202.82 R184.1
N$184
  Top 0.178: 169.51,204.19 IC40.6 168.11,204.19 167.73,203.81 167.73,202.28 168.22,201.79 C73.2 168.11,201.01 168.18,200.95 R131.1
N$185
  Top 3.81: 156.81,149.2 TP39.T@3 | TP39.T@2 156.9,149.11 156.81,149.2 | TP39.T@4 153.1,149.32 153.13,149.32 153.1,149.3 TP39.T@4 | TP39.T@1 TP39.T@4 | TP39.T@4 153.1,149.07 153.13,149.07 153.25,149.2 156.81,149.2
  Top 7.62: R132.CURRENT2 155.16,149.32
  Bottom 2.54: 155.29,149.45 155.16,149.45 | 154.87,149.24 155.07,149.24 155.29,149.45 | 155.29,149.45 155.03,149.2 156.81,149.2 TP39.T@3
  Bottom 7.62: R132.CURRENT2 155.16,149.45 155.16,149.32 | 154.87,149.24 154.87,134.71
N$186  (via drill 0.51)
  Top 0.254: R131.2 170.57,198.3 v171.54,197.33
  Bottom 0.254: TP40.T@2 171.8,134.2 171.8,134.21 171.79,134.2 | TP40.T@3 171.8,149.2 171.9,149.09 | TP40.T@3 171.54,149.2 171.42,149.07 171.29,149.2 | 171.92,149.07 171.9,149.07 TP40.T@3
  Bottom 0.381: v171.54,197.33 171.92,196.95 171.92,149.07
  Bottom 2.54: TP40.T@1 171.79,134.2 | TP40.T@2 171.9,149.09 | 171.29,149.2 TP40.T@4
N$187
  Top 0.18: J7.CONDUCTOR 186.49,218.25 186.5,218.25 184.99,216.74 R133.1
  Bottom 0.18: R168.2 196.55,211.05 195.5,210 190,210 186.5,213.5 186.5,218 186.49,218 J7.CONDUCTOR
N$188
  Top 0.178: 182.45,204.95 C75.2 R134.2 182.95,207.49 183.97,206.47 184.86,206.47 184.99,206.35 R133.2 186.7,206.41 187.02,206.09 | 187.02,206.09 D28.C | 187.02,206.09 187.02,205.2 187.91,204.31 189.3,204.31 189.43,204.19 IC42.3
N$189  (via drill 0.51)
  Top 0.178: v186.51,199.62 IC43.1
  Bottom 0.381: R137.SENSE2 186.51,189.71 189.3,192.5 189.3,194.66 186.51,197.46 v186.51,199.62
N$190  (via drill 0.51)
  Top 0.178: v185.11,199.62 184.22,200.5 182.32,200.5 182.19,200.63 IC43.8
  Bottom 0.381: R137.SENSE1 186.51,196.44 185.11,197.84 v185.11,199.62
N$191
  Top 0.178: IC43.6 184.35,201.9 184.99,201.27 IC43.2
N$192
  Top 0.178: R135.2 191.32,201 191.34,201.01 | 189.43,205.33 189.3,205.46 IC42.2 189.43,205.46 189.3,205.33 190.7,205.33 191.34,204.7 191.34,201.01 | 191.34,201.01 C76.1 189.05,201.01 187.78,202.16 187.4,202.54 187.4,203.17 187.15,203.43 184.86,203.43 183.97,202.54 IC43.5 182.06,202.82 180.07,202.82 R183.1
N$193
  Top 0.178: 194.51,204.19 IC42.6 193.11,204.19 192.73,203.81 192.73,202.28 193.22,201.79 C76.2 193.11,201.01 193.18,200.95 R136.1
N$194
  Top 3.81: 181.81,149.2 TP41.T@3 | TP41.T@2 181.9,149.11 181.81,149.2 | TP41.T@4 178.1,149.32 178.13,149.32 178.1,149.3 TP41.T@4 | TP41.T@1 TP41.T@4 | TP41.T@4 178.1,149.07 178.13,149.07 178.25,149.2 181.81,149.2
  Top 7.62: R137.CURRENT2 180.16,149.32
  Bottom 2.54: 180.29,149.45 180.16,149.45 | 179.87,149.24 180.07,149.24 180.29,149.45 | 180.29,149.45 180.03,149.2 181.81,149.2 TP41.T@3
  Bottom 7.62: R137.CURRENT2 180.16,149.45 180.16,149.32 | 179.87,149.24 179.87,134.71
N$195  (via drill 0.51)
  Top 0.254: R136.2 195.57,198.3 v196.54,197.33
  Bottom 0.254: TP42.T@2 196.8,134.2 196.8,134.21 196.79,134.2 | TP42.T@3 196.8,149.2 196.9,149.09 | TP42.T@3 196.54,149.2 196.42,149.07 196.29,149.2 | 196.92,149.07 196.9,149.07 TP42.T@3
  Bottom 0.381: v196.54,197.33 196.92,196.95 196.92,149.07
  Bottom 2.54: TP42.T@1 196.79,134.2 | TP42.T@2 196.9,149.09 | 196.29,149.2 TP42.T@4
N$196
  Top 0.18: J14.CONDUCTOR 211.49,218.25 211.5,218.25 209.99,216.74 R138.1
  Bottom 0.18: R164.2 221.55,211.05 220.5,210 215,210 211.5,213.5 211.5,218.5 211.49,218.5 J14.CONDUCTOR
N$197
  Top 0.178: 207.45,204.95 C78.2 R139.2 207.95,207.49 208.97,206.47 209.86,206.47 209.99,206.35 R138.2 211.7,206.41 212.02,206.09 | 212.02,206.09 D29.C | 212.02,206.09 212.02,205.2 212.91,204.31 214.3,204.31 214.43,204.19 IC44.3
N$198  (via drill 0.51)
  Top 0.178: v211.51,199.62 IC45.1
  Bottom 0.381: R142.SENSE2 211.51,189.71 214.3,192.5 214.3,194.66 211.51,197.46 v211.51,199.62
N$199  (via drill 0.51)
  Top 0.178: v210.11,199.62 209.22,200.5 207.32,200.5 207.19,200.63 IC45.8
  Bottom 0.381: R142.SENSE1 211.51,196.44 210.11,197.84 v210.11,199.62
N$200
  Top 0.178: IC45.6 209.35,201.9 209.99,201.27 IC45.2
N$201
  Top 0.178: R140.2 216.32,201 216.34,201.01 | 214.43,205.33 214.3,205.46 IC44.2 214.43,205.46 214.3,205.33 215.7,205.33 216.34,204.7 216.34,201.01 | 216.34,201.01 C79.1 214.05,201.01 212.78,202.16 212.4,202.54 212.4,203.17 212.15,203.43 209.86,203.43 208.97,202.54 IC45.5 207.06,202.82 205.07,202.82 R182.1
N$202
  Top 0.178: 219.51,204.19 IC44.6 218.11,204.19 217.73,203.81 217.73,202.28 218.22,201.79 C79.2 218.11,201.01 218.18,200.95 R141.1
N$203
  Top 3.81: 206.81,149.2 TP43.T@3 | TP43.T@2 206.9,149.11 206.81,149.2 | TP43.T@4 203.1,149.32 203.13,149.32 203.1,149.3 TP43.T@4 | TP43.T@1 TP43.T@4 | TP43.T@4 203.1,149.07 203.13,149.07 203.25,149.2 206.81,149.2
  Top 7.62: R142.CURRENT2 205.16,149.32
  Bottom 2.54: 205.29,149.45 205.16,149.45 | 204.87,149.24 205.07,149.24 205.29,149.45 | 205.29,149.45 205.03,149.2 206.81,149.2 TP43.T@3
  Bottom 7.62: R142.CURRENT2 205.16,149.45 205.16,149.32 | 204.87,149.24 204.87,134.71
N$204  (via drill 0.51)
  Top 0.254: R141.2 220.57,198.3 v221.54,197.33
  Bottom 0.254: TP44.T@2 221.8,134.2 221.8,134.21 221.79,134.2 | TP44.T@3 221.8,149.2 221.9,149.09 | TP44.T@3 221.54,149.2 221.42,149.07 221.29,149.2 | 221.92,149.07 221.9,149.07 TP44.T@3
  Bottom 0.381: v221.54,197.33 221.92,196.95 221.92,149.07
  Bottom 2.54: TP44.T@1 221.79,134.2 | TP44.T@2 221.9,149.09 | 221.29,149.2 TP44.T@4
N$205
  Top 0.18: J15.CONDUCTOR 236.49,218.25 236.5,218.25 234.99,216.74 R143.1
  Bottom 0.18: R166.2 246.55,211.05 245.5,210 240,210 236.5,213.5 236.5,218.5 236.49,218.5 J15.CONDUCTOR
N$206
  Top 0.178: 232.45,204.95 C81.2 R144.2 232.95,207.49 233.97,206.47 234.86,206.47 234.99,206.35 R143.2 236.7,206.41 237.02,206.09 | 237.02,206.09 D30.C | 237.02,206.09 237.02,205.2 237.91,204.31 239.3,204.31 239.43,204.19 IC46.3
N$207  (via drill 0.51)
  Top 0.178: v236.51,199.62 IC47.1
  Bottom 0.381: R147.SENSE2 236.51,189.71 239.3,192.5 239.3,194.66 236.51,197.46 v236.51,199.62
N$208  (via drill 0.51)
  Top 0.178: v235.11,199.62 234.22,200.5 232.32,200.5 232.19,200.63 IC47.8
  Bottom 0.381: R147.SENSE1 236.51,196.44 235.11,197.84 v235.11,199.62
N$209
  Top 0.178: IC47.6 234.35,201.9 234.99,201.27 IC47.2
N$210
  Top 0.178: R145.2 241.32,201 241.34,201.01 | 239.43,205.33 239.3,205.46 IC46.2 239.43,205.46 239.3,205.33 240.7,205.33 241.34,204.7 241.34,201.01 | 241.34,201.01 C82.1 239.05,201.01 237.78,202.16 237.4,202.54 237.4,203.17 237.15,203.43 234.86,203.43 233.97,202.54 IC47.5 232.06,202.82 230.07,202.82 R181.1
N$211
  Top 0.178: 244.51,204.19 IC46.6 243.11,204.19 242.73,203.81 242.73,202.28 243.22,201.79 C82.2 243.11,201.01 243.18,200.95 R146.1
N$212
  Top 3.81: 231.81,149.2 TP45.T@3 | TP45.T@2 231.9,149.11 231.81,149.2 | TP45.T@4 228.1,149.32 228.13,149.32 228.1,149.3 TP45.T@4 | TP45.T@1 TP45.T@4 | TP45.T@4 228.1,149.07 228.13,149.07 228.25,149.2 231.81,149.2
  Top 7.62: R147.CURRENT2 230.16,149.32
  Bottom 2.54: 230.29,149.45 230.16,149.45 | 229.87,149.24 230.07,149.24 230.29,149.45 | 230.29,149.45 230.03,149.2 231.81,149.2 TP45.T@3
  Bottom 7.62: R147.CURRENT2 230.16,149.45 230.16,149.32 | 229.87,149.24 229.87,134.71
N$213  (via drill 0.51)
  Top 0.254: R146.2 245.57,198.3 v246.54,197.33
  Bottom 0.254: TP46.T@2 246.8,134.2 246.8,134.21 246.79,134.2 | TP46.T@3 246.8,149.2 246.9,149.09 | TP46.T@3 246.54,149.2 246.42,149.07 246.29,149.2 | 246.92,149.07 246.9,149.07 TP46.T@3
  Bottom 0.381: v246.54,197.33 246.92,196.95 246.92,149.07
  Bottom 2.54: TP46.T@1 246.79,134.2 | TP46.T@2 246.9,149.09 | 246.29,149.2 TP46.T@4
N$214
  Top 0.18: J16.CONDUCTOR 261.49,218.25 261.5,218.25 259.99,216.74 R148.1
  Bottom 0.18: R169.2 271.55,211.05 270.5,210 265,210 261.5,213.5 261.5,218.5 261.49,218.5 J16.CONDUCTOR
N$215
  Top 0.178: 257.45,204.95 C84.2 R149.2 257.95,207.49 258.97,206.47 259.86,206.47 259.99,206.35 R148.2 261.7,206.41 262.02,206.09 | 262.02,206.09 D31.C | 262.02,206.09 262.02,205.2 262.91,204.31 264.3,204.31 264.43,204.19 IC48.3
N$216  (via drill 0.51)
  Top 0.178: v261.51,199.62 IC49.1
  Bottom 0.381: R152.SENSE2 261.51,189.71 264.3,192.5 264.3,194.66 261.51,197.46 v261.51,199.62
N$217  (via drill 0.51)
  Top 0.178: v260.11,199.62 259.22,200.5 257.32,200.5 257.19,200.63 IC49.8
  Bottom 0.381: R152.SENSE1 261.51,196.44 260.11,197.84 v260.11,199.62
N$218
  Top 0.178: IC49.6 259.35,201.9 259.99,201.27 IC49.2
N$219
  Top 0.178: R150.2 266.32,201 266.34,201.01 | 264.43,205.33 264.3,205.46 IC48.2 264.43,205.46 264.3,205.33 265.7,205.33 266.34,204.7 266.34,201.01 | 266.34,201.01 C85.1 264.05,201.01 262.78,202.16 262.4,202.54 262.4,203.17 262.14,203.43 259.86,203.43 258.97,202.54 IC49.5 257.06,202.82 255.07,202.82 R180.1
N$220
  Top 0.178: 269.51,204.19 IC48.6 268.11,204.19 267.73,203.81 267.73,202.28 268.22,201.79 C85.2 268.11,201.01 268.18,200.95 R151.1
N$221
  Top 3.81: 256.81,149.2 TP47.T@3 | TP47.T@2 256.9,149.11 256.81,149.2 | TP47.T@4 253.1,149.32 253.13,149.32 253.1,149.3 TP47.T@4 | TP47.T@1 TP47.T@4 | TP47.T@4 253.1,149.07 253.13,149.07 253.25,149.2 256.81,149.2
  Top 7.62: R152.CURRENT2 255.16,149.32
  Bottom 2.54: 255.29,149.45 255.16,149.45 | 254.87,149.24 255.07,149.24 255.29,149.45 | 255.29,149.45 255.03,149.2 256.81,149.2 TP47.T@3
  Bottom 7.62: R152.CURRENT2 255.16,149.45 255.16,149.32 | 254.87,149.24 254.87,134.71
N$222  (via drill 0.51)
  Top 0.254: R151.2 270.57,198.3 v271.54,197.33
  Bottom 0.254: TP48.T@2 271.8,134.2 271.8,134.21 271.79,134.2 | TP48.T@3 271.8,149.2 271.9,149.09 | TP48.T@3 271.54,149.2 271.42,149.2 271.29,149.2 | 271.92,149.07 271.9,149.07 TP48.T@3
  Bottom 0.381: v271.54,197.33 271.92,196.95 271.92,149.07
  Bottom 2.54: TP48.T@1 271.79,134.2 | TP48.T@2 271.9,149.09 | 271.29,149.2 TP48.T@4
N$223
  Top 0.18: J17.CONDUCTOR 286.49,218.25 286.5,218.25 284.99,216.74 R153.1
  Bottom 0.18: R163.2 296.55,211.05 295.5,210 290,210 286.5,213.5 286.5,218.5 286.49,218.5 J17.CONDUCTOR
N$224
  Top 0.178: 282.45,204.95 C87.2 R154.2 282.95,207.49 283.97,206.47 284.86,206.47 284.99,206.35 R153.2 286.7,206.41 287.02,206.09 | 287.02,206.09 D32.C | 287.02,206.09 287.02,205.2 287.91,204.31 289.3,204.31 289.43,204.19 IC50.3
N$225  (via drill 0.51)
  Top 0.178: v286.51,199.62 IC51.1
  Bottom 0.381: R157.SENSE2 286.51,189.71 289.3,192.5 289.3,194.66 286.51,197.46 v286.51,199.62
N$226  (via drill 0.51)
  Top 0.178: v285.11,199.62 284.22,200.5 282.32,200.5 282.19,200.63 IC51.8
  Bottom 0.381: R157.SENSE1 286.51,196.44 285.11,197.84 v285.11,199.62
N$227
  Top 0.178: IC51.6 284.35,201.9 284.99,201.27 IC51.2
N$228
  Top 0.178: R155.2 291.32,201 291.34,201.01 | 289.43,205.33 289.3,205.46 IC50.2 289.43,205.46 289.3,205.33 290.7,205.33 291.34,204.7 291.34,201.01 | 291.34,201.01 C88.1 289.05,201.01 287.78,202.16 287.4,202.54 287.4,203.17 287.14,203.43 284.86,203.43 283.97,202.54 IC51.5 282.06,202.82 280.07,202.82 | 280.07,202.82 280.04,202.82 | R179.1 280.07,202.82
N$229
  Top 0.178: 294.51,204.19 IC50.6 293.11,204.19 292.73,203.81 292.73,202.28 293.22,201.79 C88.2 293.11,201.01 293.18,200.95 R156.1
N$230
  Top 3.81: 281.81,149.2 TP49.T@3 | TP49.T@2 281.9,149.11 281.81,149.2 | TP49.T@4 278.1,149.32 278.13,149.32 278.1,149.3 TP49.T@4 | TP49.T@1 TP49.T@4 | TP49.T@4 278.1,149.07 278.13,149.07 278.25,149.2 281.81,149.2
  Top 7.62: R157.CURRENT2 280.16,149.32
  Bottom 2.54: 280.29,149.45 280.16,149.45 | 279.87,149.24 280.07,149.24 280.29,149.45 | 280.29,149.45 280.03,149.2 281.81,149.2 TP49.T@3
  Bottom 7.62: R157.CURRENT2 280.16,149.45 280.16,149.32 | 279.87,149.24 279.87,134.71
N$231  (via drill 0.51)
  Top 0.254: R156.2 295.57,198.3 v296.54,197.33
  Bottom 0.254: TP50.T@2 296.8,134.2 296.8,134.21 296.79,134.2 | TP50.T@3 296.8,149.2 296.9,149.09 | TP50.T@3 296.54,149.2 296.42,149.2 296.29,149.2 | 296.92,149.07 296.9,149.07 TP50.T@3
  Bottom 0.381: v296.54,197.33 296.92,196.95 296.92,149.07
  Bottom 2.54: TP50.T@1 296.79,134.2 | TP50.T@2 296.9,149.09 | 296.29,149.2 TP50.T@4
N$232
  Top 0.18: J18.CONDUCTOR 311.49,218.25 311.5,218.25 309.99,216.74 R158.1
  Bottom 0.18: R167.2 322,211 321.5,211 320.5,210 315,210 311.5,213.5 311.5,218.5 311.49,218.5 J18.CONDUCTOR
N$233
  Top 0.178: 307.45,204.95 C90.2 R159.2 307.95,207.49 308.97,206.47 309.86,206.47 309.99,206.35 R158.2 311.7,206.41 312.02,206.09 | 312.02,206.09 D33.C | 312.02,206.09 312.02,205.2 312.91,204.31 314.3,204.31 314.43,204.19 IC52.3
N$234  (via drill 0.51)
  Top 0.178: IC53.1 v311.51,199.62
  Bottom 0.381: R162.SENSE2 311.51,189.71 314.3,192.5 314.3,194.66 311.51,197.46 v311.51,199.62
N$235  (via drill 0.51)
  Top 0.178: v310.11,199.62 309.22,200.5 307.32,200.5 307.19,200.63 IC53.8
  Bottom 0.381: R162.SENSE1 311.51,196.44 310.11,197.84 v310.11,199.62
N$236
  Top 0.178: IC53.6 309.35,201.9 309.99,201.27 IC53.2
N$237
  Top 0.178: R160.2 316.32,201 316.34,201.01 | 314.43,205.33 314.3,205.46 IC52.2 314.43,205.46 314.3,205.33 315.7,205.33 316.34,204.7 316.34,201.01 | 316.34,201.01 C91.1 314.05,201.01 312.78,202.16 312.4,202.54 312.4,203.17 312.14,203.43 309.86,203.43 308.97,202.54 IC53.5 307.06,202.82 305.07,202.82 | 305.07,202.82 304.93,202.82 | 305.07,202.82 R178.1
N$238
  Top 0.178: 319.51,204.19 IC52.6 318.11,204.19 317.73,203.81 317.73,202.28 318.22,201.79 C91.2 318.11,201.01 318.18,200.95 R161.1
N$239
  Top 3.81: 306.81,149.2 TP51.T@3 | TP51.T@2 306.9,149.11 306.81,149.2 | TP51.T@4 303.1,149.32 303.13,149.32 303.1,149.3 TP51.T@4 | TP51.T@1 TP51.T@4 | TP51.T@4 303.1,149.07 303.13,149.07 303.25,149.2 306.81,149.2
  Top 7.62: R162.CURRENT2 305.16,149.32
  Bottom 2.54: 305.29,149.45 305.16,149.45 | 304.87,149.24 305.07,149.24 305.29,149.45 | 305.29,149.45 305.03,149.2 306.81,149.2 TP51.T@3
  Bottom 7.62: R162.CURRENT2 305.16,149.45 305.16,149.32 | 304.87,149.24 304.87,134.71
N$240  (via drill 0.51)
  Top 0.254: R161.2 320.57,198.3 v321.54,197.33
  Bottom 0.254: TP52.T@2 321.8,134.2 321.8,134.21 321.79,134.2 | TP52.T@3 321.8,149.2 321.9,149.09 | TP52.T@3 321.54,149.2 321.42,149.2 321.29,149.2 | 321.92,149.07 321.9,149.07 TP52.T@3
  Bottom 0.381: v321.54,197.33 321.92,196.95 321.92,149.07
  Bottom 2.54: 321.79,134.2 TP52.T@1 | 321.9,149.09 TP52.T@2 | 321.29,149.2 TP52.T@4
N$241
  Top 1: 325,116 325,127
N$242
  Top 1: 300,116 300,127
N$243
  Top 1: 250,116 250,127
N$244
  Top 1: 275,116 275,127
N$245
  Top 1: 225,116 225,127
N$246
  Top 1: 200,116 200,127
N$247
  Top 1: 175,116 175,127
N$248
  Top 1: 150,116 150,127
N$249
  Top 1: 125,116 125,127
N$250
  Top 1: 100,116 100,127
N$251
  Top 1: 75,116 75,127
N$252
  Top 1: 50,116 50,127
N$253
  Top 1: 25,116 25,127
N$254
  Bottom 0.36: +SUPPLY.TP 347.25,189.25 349,187.5 349,183.9 349.2,183.7 349.25,183.8 F2.1A
N$255  (via drill 0.71)
  Top 0.381: C92.2 IC54.3
  Top 0.4: C92.2 344.2,204.6 v344.2,201.3
  Bottom 0.4: F2.2A D34.2 | D34.2 329,191.4 | D34.2 328.93,188.8 344.2,188.8 v344.2,201.3
N$256
  Top 0.178: C94.2 336.49,206.95 336.49,208.92 R177.2 337.44,207.9 IC54.1 339.53,207.65 339.53,205.11 R176.1
N$257
  Bottom 0.18: R167.1 322,213 321.9,213.1 D35.A
N$258
  Bottom 0.18: R163.1 297,213 296.9,213.1 D38.A
N$259
  Bottom 0.18: R169.1 272,213 271.9,213.1 D40.A
N$260
  Bottom 0.18: R166.1 247,213 246.9,213.1 D36.A
N$261
  Bottom 0.18: R164.1 222,213 221.9,213.1 D39.A
N$262
  Bottom 0.18: R168.1 197,213 196.9,213.1 D41.A
N$263
  Bottom 0.18: R165.1 172,213 171.9,213.1 D37.A
N$264
  Bottom 0.18: R170.1 147,213 146.9,213.1 D42.A
N$265
  Bottom 0.18: R171.1 72,213 71.9,213.1 D43.A
N$266
  Bottom 0.18: R173.1 47,213 46.9,213.1 D45.A
N$267
  Bottom 0.18: R172.1 122,213 121.9,213.1 D44.A
N$268
  Bottom 0.18: R175.1 97,213 96.9,213.1 D47.A
N$269
  Bottom 0.18: R174.1 22,213 21.9,213.1 D46.A
S$1
  Top 0.18: 318,0 318,114
S$2
  Top 0.18: 306,114 317,114
S$3
  Top 0.18: 319,114 360,114
S$4
  Bottom 0.203: 0.1,0.74 0.1,0.1 0.74,0.1
S$5
  Bottom 0.203: 359.26,0.1 359.89,0.1 359.89,0.74
S$6
  Bottom 0.203: 0.74,226.9 0.1,226.9 0.1,226.26
S$7
  Bottom 0.203: 359.23,226.87 359.87,226.87 359.87,226.24
S$8
  Top 0.203: 0.74,226.9 0.1,226.9 0.1,226.26
S$9
  Top 0.203: 0.1,0.74 0.1,0.1 0.74,0.1
S$10
  Top 0.203: 359.26,0.1 359.89,0.1 359.89,0.74
S$11
  Top 0.203: 359.87,226.24 359.87,226.87 359.23,226.87

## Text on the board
Top: CATS - Unipolar Rev:A1 | Cold Atoms Transfer System | J. Thywissen Labs | University of Toronto - Physics | 13 | 12 | 11 | 10 | 9 | 8 | 7 | 6 | 5 | 4 | 3 | 2 | 1 | Com | CATS - Bipolar Rev:A1 | Cold Atoms Transfer System | J. Thywissen Labs | University of Toronto - Physics | G1+L | G1+U | D1 | G1-U | G1-L | G2+L | G2+U | D2 | G2-U | G2-L | G3+L | G3+U | D3 | G3-U | G3-L | G4+L | G4+U | D4 | G4-U | G4-L | G5+L | G5+U | D5 | G5-U | G5-L | Com
tDocu: CATS - Combined | Cold Atoms Transfer System | A1 | 0.18mm(0.0071") | 7.5mm(0.295") | 0.18mm(0.0071") | n/a | 1mm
